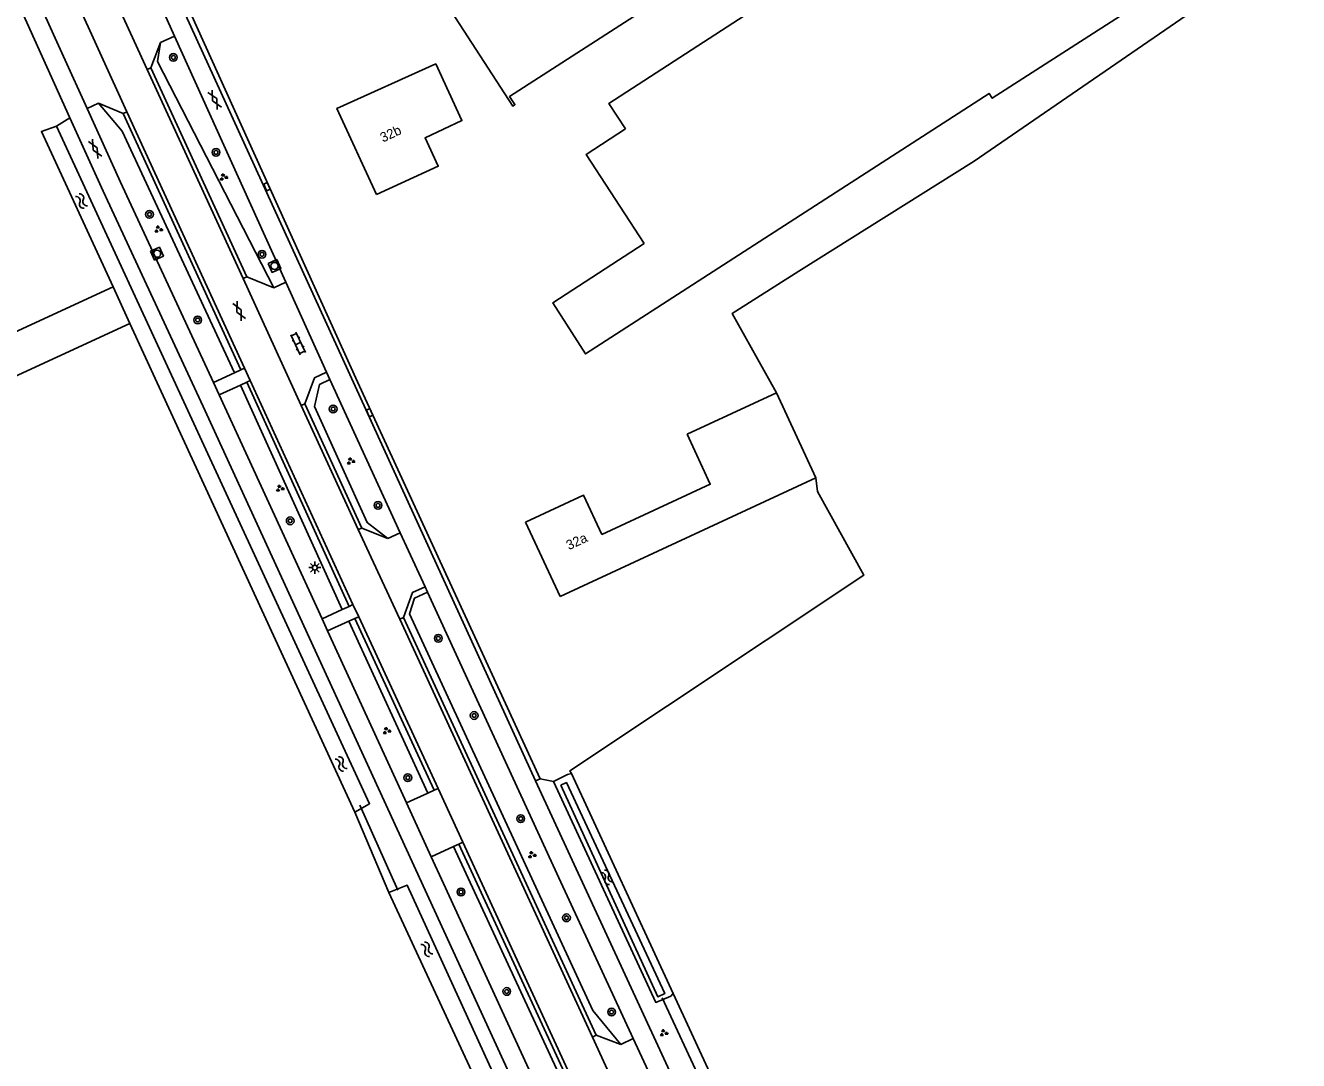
# Model space of a CAD drawing. Extents: x 134297 to 137000, y 403500 to 406000.
# Drawn here: x 136113.5 to 136245.2, y 404648.7 to 404755.7 of the extents above; entities that cross this region are included whole.
import ezdxf

# ---------------------------------------------------------------- set-up
doc = ezdxf.new("R2010")
doc.units = 0
for name, color, linetype in [('gg-anno-huisnummerreeks BGT', 7, 'Continuous'), ('gg-bbg-bijgebouw', 7, 'Continuous'), ('gg-bbg-gedigitaliseerde bebouwing', 7, 'Continuous'), ('gg-bbg-hoofdgebouw', 7, 'Continuous'), ('gg-knt-bronhoudergrens', 7, 'Continuous'), ('gg-knt-verharding', 7, 'Continuous'), ('gg-kntw-bovenkant insteek waterloop', 7, 'Continuous'), ('gg-kntw-waterlijn', 7, 'Continuous'), ('gg-kwrk-duiker nz buis', 7, 'Continuous'), ('gt-grn-groengrens', 7, 'Continuous'), ('gt-grn-vlakafsluiter', 7, 'Continuous'), ('gt-symb-boom', 7, 'Continuous'), ('gt-symb-gesloten verharding', 7, 'Continuous'), ('gt-symb-groenvak', 7, 'Continuous'), ('gt-symb-klinker verharding', 7, 'Continuous'), ('gt-symb-kolk', 7, 'Continuous'), ('gt-symb-lichtmast', 7, 'Continuous'), ('gt-symb-rioolschacht', 7, 'Continuous'), ('gt-symb-watersymbool', 7, 'Continuous')]:
    doc.layers.add(name, color=color, linetype=linetype)

# ---------------------------------------------------------------- blocks, each defined once
blk = doc.blocks.new('gt0-GRVAK')
at = {"layer": 'gt-symb-groenvak'}
for p, q in [((-0.11, 0.19), (-0.23, 0.24)), ((-0.18, 0.15), (0.09, 0.15)), ((-0.09, 0.21), (-0.16, 0.32)), ((-0.05, 0.21), (-0.05, 0.39)), ((0, 0.21), (0.06, 0.32)), ((0.01, 0.19), (0.13, 0.24)), ((0.26, -0.05), (0.2, 0.06)), ((0.3, -0.05), (0.3, 0.13)), ((0.35, -0.05), (0.41, 0.06)), ((-0.24, -0.23), (-0.36, -0.18)), ((-0.32, -0.26), (-0.05, -0.26)), ((-0.23, -0.21), (-0.29, -0.09)), ((-0.18, -0.2), (-0.18, -0.02)), ((-0.14, -0.21), (-0.07, -0.09)), ((-0.12, -0.23), (0, -0.18)), ((0.24, -0.07), (0.12, -0.02)), ((0.17, -0.11), (0.44, -0.11)), ((0.37, -0.07), (0.49, -0.02))]:
    blk.add_line(p, q, dxfattribs=at)
blk = doc.blocks.new('gt0-BOOM')
at = {"layer": 'gt-symb-boom'}
for radius in [0.4, 0.2]:
    blk.add_circle((0, 0), radius, dxfattribs=at)
blk = doc.blocks.new('gt0-WA')
at = {"layer": 'gt-symb-watersymbool'}
for centre, start, end in [((-0.32, 0.02), 28.0725, 151.9275), ((0.43, 0.42), 208.0725, 331.9275), ((-0.32, -0.43), 28.0725, 151.9275), ((0.43, -0.03), 208.0725, 331.9275)]:
    blk.add_arc(centre, 0.425, start, end, dxfattribs=at)
blk = doc.blocks.new('gt0-KOLK')
at = {"layer": 'gt-symb-kolk'}
blk.add_lwpolyline([(0, 0), (0.38, 0), (0.38, 0.4), (-0.38, 0.4), (-0.38, 0), (0, 0)], dxfattribs=at)
blk = doc.blocks.new('gt0-GESVH1')
at = {"layer": 'gt-symb-gesloten verharding'}
for p, q in [((-0.99, -0.26), (0.01, 0.24)), ((0.01, -0.26), (-0.99, 0.24)), ((0.01, 0.24), (1.01, -0.26)), ((1.01, 0.24), (0.01, -0.26))]:
    blk.add_line(p, q, dxfattribs=at)
blk = doc.blocks.new('gt0-KL1')
at = {"layer": 'gt-symb-klinker verharding'}
for p, q in [((-1.15, 0.3), (1.15, 0.3)), ((-1, -0.3), (-1, 0.3)), ((-0.5, 0.3), (-0.5, 0.45)), ((0, -0.3), (0, 0.3)), ((0.5, 0.3), (0.5, 0.45)), ((1, -0.3), (1, 0.3)), ((-1.15, -0.3), (1.15, -0.3)), ((-0.5, -0.45), (-0.5, -0.3)), ((0.5, -0.45), (0.5, -0.3))]:
    blk.add_line(p, q, dxfattribs=at)
blk = doc.blocks.new('gt0-RS')
at = {"layer": 'gt-symb-rioolschacht'}
blk.add_lwpolyline([(-0.5, -0.5), (0.5, -0.5), (0.5, 0.5), (-0.5, 0.5)], close=True, dxfattribs=at)
blk.add_circle((0, 0), 0.375, dxfattribs=at)
blk = doc.blocks.new('gt0-LMAST')
at = {"layer": 'gt-symb-lichtmast'}
for p, q in [((-0.18, 0.17), (-0.45, 0.44)), ((-0.01, 0.25), (-0.01, 0.62)), ((0.17, 0.17), (0.44, 0.44)), ((-0.26, 0), (-0.63, 0)), ((-0.18, -0.18), (-0.45, -0.45)), ((-0.01, -0.25), (-0.01, -0.63)), ((0.44, -0.45), (0.17, -0.18)), ((0.24, 0), (0.62, 0))]:
    blk.add_line(p, q, dxfattribs=at)
blk.add_circle((-0.01, 0), 0.25, dxfattribs=at)

msp = doc.modelspace()

# ---------------------------------------------------------------- linework, layer by layer
at = {"layer": 'gg-bbg-bijgebouw'}
for points in [[(136155.47, 404760.48), (136163.93, 404747.4), (136164.16, 404747.55), (136163.61, 404748.38), (136201.31, 404772.69), (136193.43, 404784.95), (136155.47, 404760.48)], [(136175.58, 404745.03), (136173.86, 404747.66), (136201.97, 404765.89), (136201.65, 404766.39), (136223.97, 404780.8), (136235.8, 404762.57), (136213.51, 404748.2), (136213.18, 404748.7), (136171.47, 404721.76), (136168.07, 404727.04), (136177.52, 404733.18)], [(136177.52, 404733.18), (136171.53, 404742.39), (136175.58, 404745.03)]]:
    msp.add_lwpolyline(points, dxfattribs=at)
at = {"layer": 'gg-bbg-gedigitaliseerde bebouwing'}
for p, q in [((136191.19, 404717.73), (136181.96, 404713.45)), ((136191.19, 404717.73), (136195.27, 404708.94)), ((136195.27, 404708.94), (136168.84, 404696.67))]:
    msp.add_line(p, q, dxfattribs=at)
for points in [[(136173.14, 404703.08), (136184.36, 404708.28), (136181.96, 404713.45)], [(136165.26, 404704.37), (136171.24, 404707.16), (136173.14, 404703.08)]]:
    msp.add_lwpolyline(points, dxfattribs=at)
at = {"layer": 'gg-bbg-hoofdgebouw'}
msp.add_line((136168.84, 404696.67), (136165.26, 404704.37), dxfattribs=at)
msp.add_lwpolyline([(136149.85, 404738.26), (136156.22, 404741.17), (136154.86, 404744.12), (136158.67, 404745.89), (136155.97, 404751.75), (136145.75, 404747.15), (136149.85, 404738.26)], dxfattribs=at)
at = {"layer": 'gg-knt-bronhoudergrens'}
msp.add_line((136107.45, 404721.72), (136122.6, 404728.69), dxfattribs=at)
for points in [[(136317.98, 404877.07), (136319.47, 404878.08), (136322.79, 404873.18), (136330.65, 404863.19), (136313.19, 404850.76), (136274.43, 404824.83), (136294.8, 404795.99), (136287.84, 404789.14), (136272.48, 404780.34), (136263.09, 404775.03), (136261.31, 404774.23), (136257.93, 404774.49), (136252.31, 404769.75), (136242.58, 404763.02), (136211.65, 404741.71), (136193.52, 404730.34), (136186.61, 404725.94), (136191.19, 404717.73)], [(135916.45, 404629), (135940.08, 404639.92), (136124.35, 404724.9)], [(136195.27, 404708.94), (136195.43, 404707.53), (136200.23, 404698.88), (136169.84, 404678.65), (136169.99, 404678.36)]]:
    msp.add_lwpolyline(points, dxfattribs=at)
at = {"layer": 'gg-knt-verharding'}
for p, q in [((136124.04, 404746.8), (136116.94, 404762.4)), ((136126.14, 404751.19), (136121.43, 404761.45)), ((136126.11, 404760.94), (136128.97, 404754.62)), ((136114.48, 404759.17), (136116.62, 404754.43)), ((136130.11, 404756.85), (136166.28, 404677.6)), ((136117.49, 404752.52), (136116.62, 404754.43)), ((136126.51, 404751.37), (136127.51, 404753.96)), ((136127.51, 404753.96), (136128.97, 404754.62)), ((136128.97, 404754.62), (136140.47, 404729.18)), ((136119.91, 404747.16), (136117.49, 404752.52)), ((136126.14, 404751.19), (136126.51, 404751.37)), ((136136.06, 404729.57), (136126.14, 404751.19)), ((136136.43, 404729.74), (136126.51, 404751.37)), ((136121.1, 404747.69), (136119.91, 404747.16)), ((136121.1, 404747.69), (136123.66, 404746.64)), ((136124.04, 404746.8), (136123.66, 404746.64)), ((136123.66, 404746.64), (136135.82, 404720.12)), ((136136.18, 404720.3), (136124.04, 404746.8)), ((136136.43, 404729.74), (136136.06, 404729.57)), ((136142.06, 404716.42), (136136.06, 404729.57)), ((136139.21, 404728.61), (136136.43, 404729.74)), ((136139.21, 404728.61), (136140.47, 404729.18)), ((136140.47, 404729.18), (136144.68, 404719.87)), ((136135.16, 404719.81), (136132.98, 404718.8)), ((136135.82, 404720.12), (136135.16, 404719.81)), ((136135.82, 404720.12), (136136.18, 404720.3)), ((136136.18, 404720.3), (136136.77, 404719.01)), ((136144.68, 404719.87), (136145.03, 404719.11)), ((136132.98, 404718.8), (136133.57, 404717.53)), ((136135.78, 404718.55), (136133.57, 404717.53)), ((136135.78, 404718.55), (136136.42, 404718.84)), ((136136.42, 404718.84), (136136.77, 404719.01)), ((136147.02, 404695.66), (136136.42, 404718.84)), ((136136.77, 404719.01), (136147.41, 404695.84)), ((136145.03, 404719.11), (136152.3, 404703.25)), ((136133.57, 404717.53), (136144.21, 404694.37)), ((136142.06, 404716.42), (136142.42, 404716.59)), ((136147.96, 404703.59), (136142.06, 404716.42)), ((136148.33, 404703.76), (136142.42, 404716.59)), ((136147.96, 404703.59), (136148.33, 404703.76)), ((136152.27, 404694.33), (136147.96, 404703.59)), ((136148.33, 404703.76), (136151.03, 404702.67)), ((136151.03, 404702.67), (136152.3, 404703.25)), ((136152.3, 404703.25), (136154.86, 404697.68)), ((136154.86, 404697.68), (136155.11, 404697.12)), ((136147.02, 404695.66), (136146.3, 404695.33)), ((136147.41, 404695.84), (136147.02, 404695.66)), ((136147.41, 404695.84), (136148, 404694.59)), ((136146.3, 404695.33), (136144.21, 404694.37)), ((136144.21, 404694.37), (136144.79, 404693.11)), ((136147.61, 404694.39), (136146.97, 404694.11)), ((136148, 404694.59), (136147.61, 404694.39)), ((136155.81, 404676.66), (136147.61, 404694.39)), ((136156.21, 404676.83), (136148, 404694.59)), ((136152.62, 404694.51), (136152.27, 404694.33)), ((136172.17, 404651.11), (136152.27, 404694.33)), ((136172.54, 404651.31), (136152.62, 404694.51)), ((136146.97, 404694.11), (136144.79, 404693.11)), ((136144.79, 404693.11), (136152.39, 404676.55)), ((136166.28, 404677.6), (136166.75, 404677.81)), ((136193.43, 404618.96), (136166.28, 404677.6)), ((136152.39, 404676.55), (136152.95, 404675.33)), ((136155.14, 404676.33), (136152.95, 404675.33)), ((136155.81, 404676.66), (136155.14, 404676.33)), ((136156.21, 404676.83), (136155.81, 404676.66)), ((136158.76, 404671.27), (136156.21, 404676.83)), ((136152.95, 404675.33), (136155.51, 404669.77)), ((136157.8, 404670.82), (136155.51, 404669.77)), ((136158.36, 404671.08), (136157.8, 404670.82)), ((136158.36, 404671.08), (136158.76, 404671.27)), ((136155.51, 404669.77), (136156.78, 404667.01)), ((136156.78, 404667.01), (136190.96, 404592.6)), ((136172.54, 404651.31), (136172.17, 404651.11)), ((136176.24, 404642.22), (136172.17, 404651.11)), ((136175.12, 404650.36), (136172.54, 404651.31)), ((136175.12, 404650.36), (136176.39, 404650.95)), ((136176.39, 404650.95), (136178.85, 404645.64))]:
    msp.add_line(p, q, dxfattribs=at)
for points in [[(136118.15, 404746.18), (136112.91, 404757.79), (136112.42, 404757.57), (136112.12, 404758.22)], [(136130.56, 404757.11), (136147.89, 404718.88), (136166.75, 404677.81)], [(136119.91, 404747.16), (136123.36, 404739.54), (136132.98, 404718.8)], [(136189.8, 404590.23), (136131.92, 404716.32), (136121.59, 404738.59), (136118.15, 404746.18)], [(136142.42, 404716.59), (136143.42, 404719.3), (136144.68, 404719.87)], [(136152.62, 404694.51), (136153.58, 404697.1), (136154.86, 404697.68)], [(136155.11, 404697.12), (136168.68, 404667.57), (136176.39, 404650.95)], [(136194.08, 404594.02), (136172.46, 404640.54), (136158.36, 404671.08)], [(136194.45, 404594.19), (136172.82, 404640.71), (136158.76, 404671.27)]]:
    msp.add_lwpolyline(points, dxfattribs=at)
at = {"layer": 'gg-kntw-bovenkant insteek waterloop'}
for p, q in [((136124.35, 404724.9), (136122.6, 404728.69)), ((136124.35, 404724.9), (136128.79, 404715.26)), ((136128.79, 404715.26), (136147.61, 404674.39)), ((136180.52, 404655.61), (136169.99, 404678.36)), ((136151.11, 404666.07), (136185.66, 404591.52)), ((136180.52, 404655.61), (136180.27, 404655.36))]:
    msp.add_line(p, q, dxfattribs=at)
for points in [[(136122.6, 404728.69), (136115.2, 404744.76), (136116.74, 404745.33)], [(136147.61, 404674.39), (136149.12, 404675.25), (136116.74, 404745.33)], [(136169.99, 404678.36), (136169.59, 404678.26), (136168.16, 404677.53)], [(136180.27, 404655.36), (136178.71, 404654.69), (136168.16, 404677.53)], [(136185.66, 404591.52), (136187.13, 404592.18), (136153, 404666.84), (136151.11, 404666.07)]]:
    msp.add_lwpolyline(points, dxfattribs=at)
at = {"layer": 'gg-kntw-waterlijn'}
msp.add_lwpolyline([(136168.91, 404677.17), (136178.92, 404655.28), (136179.64, 404655.61), (136169.48, 404677.44), (136168.91, 404677.17)], dxfattribs=at)
at = {"layer": 'gg-kwrk-duiker nz buis'}
for p, q in [((136152.04, 404666.3), (136148.13, 404675.08)), ((136179.37, 404655.16), (136183.49, 404646.36))]:
    msp.add_line(p, q, dxfattribs=at)
at = {"layer": 'gt-grn-groengrens'}
for p, q in [((136116.74, 404745.33), (136118.15, 404746.18)), ((136146.3, 404695.33), (136135.78, 404718.55)), ((136155.14, 404676.33), (136146.97, 404694.11)), ((136166.75, 404677.81), (136168.16, 404677.53)), ((136151.11, 404666.07), (136147.61, 404674.39))]:
    msp.add_line(p, q, dxfattribs=at)
for points in [[(136139.21, 404728.61), (136127.19, 404752.02), (136127.51, 404753.96)], [(136135.16, 404719.81), (136123.56, 404744.81), (136121.1, 404747.69)], [(136145.03, 404719.11), (136143.95, 404718.62), (136143.43, 404716.33), (136148.88, 404704.32), (136151.03, 404702.67)], [(136175.12, 404650.36), (136172.22, 404653.85), (136153.26, 404694.89), (136153.76, 404696.5), (136155.11, 404697.12)], [(136193.38, 404593.71), (136171.94, 404640.3), (136157.8, 404670.82)]]:
    msp.add_lwpolyline(points, dxfattribs=at)
at = {"layer": 'gt-grn-vlakafsluiter'}
msp.add_line((136184.52, 404646.96), (136180.52, 404655.61), dxfattribs=at)

# ---------------------------------------------------------------- block references
at = {"layer": 'gt-symb-boom'}
for p in [(136128.84, 404752.43), (136133.25, 404742.61), (136126.37, 404736.2), (136138, 404732.07), (136131.35, 404725.28), (136145.36, 404716.07), (136150, 404706.1), (136140.92, 404704.5), (136156.23, 404692.35), (136159.94, 404684.37), (136153.08, 404677.94), (136164.76, 404673.7), (136158.58, 404666.12), (136169.49, 404663.45), (136163.31, 404655.83), (136174.15, 404653.7)]:
    msp.add_blockref('gt0-BOOM', p, dxfattribs=at)
at = {"layer": 'gt-symb-gesloten verharding'}
for p, rotation in [((136133.1, 404748.04), 118.99897714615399), ((136120.75, 404742.96), 118.99897714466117), ((136135.63, 404726.19), 115.97571465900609)]:
    msp.add_blockref('gt0-GESVH1', p, dxfattribs=dict(at, rotation=rotation))
at = {"layer": 'gt-symb-groenvak'}
for p in [(136134.02, 404740.04), (136127.28, 404734.65), (136147.16, 404710.67), (136139.84, 404707.85), (136150.88, 404682.78), (136165.9, 404669.94), (136179.53, 404651.53)]:
    msp.add_blockref('gt0-GRVAK', p, dxfattribs=at)
at = {"layer": 'gt-symb-klinker verharding', "rotation": 115.02727879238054}
msp.add_blockref('gt0-KL1', (136141.73, 404722.84), dxfattribs=at)
at = {"layer": 'gt-symb-kolk', "rotation": -65.35690478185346}
for p in [(136138.34, 404738.98), (136148.95, 404715.6)]:
    msp.add_blockref('gt0-KOLK', p, dxfattribs=at)
at = {"layer": 'gt-symb-lichtmast'}
msp.add_blockref('gt0-LMAST', (136143.48, 404699.66), dxfattribs=at)
at = {"layer": 'gt-symb-rioolschacht'}
for p, rotation in [((136127.15, 404732.13), -65.35690478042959), ((136139.29, 404730.86), -65.35690478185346)]:
    msp.add_blockref('gt0-RS', p, dxfattribs=dict(at, rotation=rotation))
at = {"layer": 'gt-symb-watersymbool', "rotation": 126.01052540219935}
for p in [(136119.37, 404737.52), (136146.21, 404679.32), (136173.69, 404667.59), (136155.09, 404660.15)]:
    msp.add_blockref('gt0-WA', p, dxfattribs=at)

# ---------------------------------------------------------------- texts
at = {"layer": 'gg-anno-huisnummerreeks BGT'}
for s, rotation, p in [('32b', 24.8, (136150.5, 404743.62)), ('32a', 25, (136169.74, 404701.46))]:
    msp.add_text(s, height=1, rotation=rotation, dxfattribs=at).set_placement(p)

doc.saveas('drawing.dxf')
